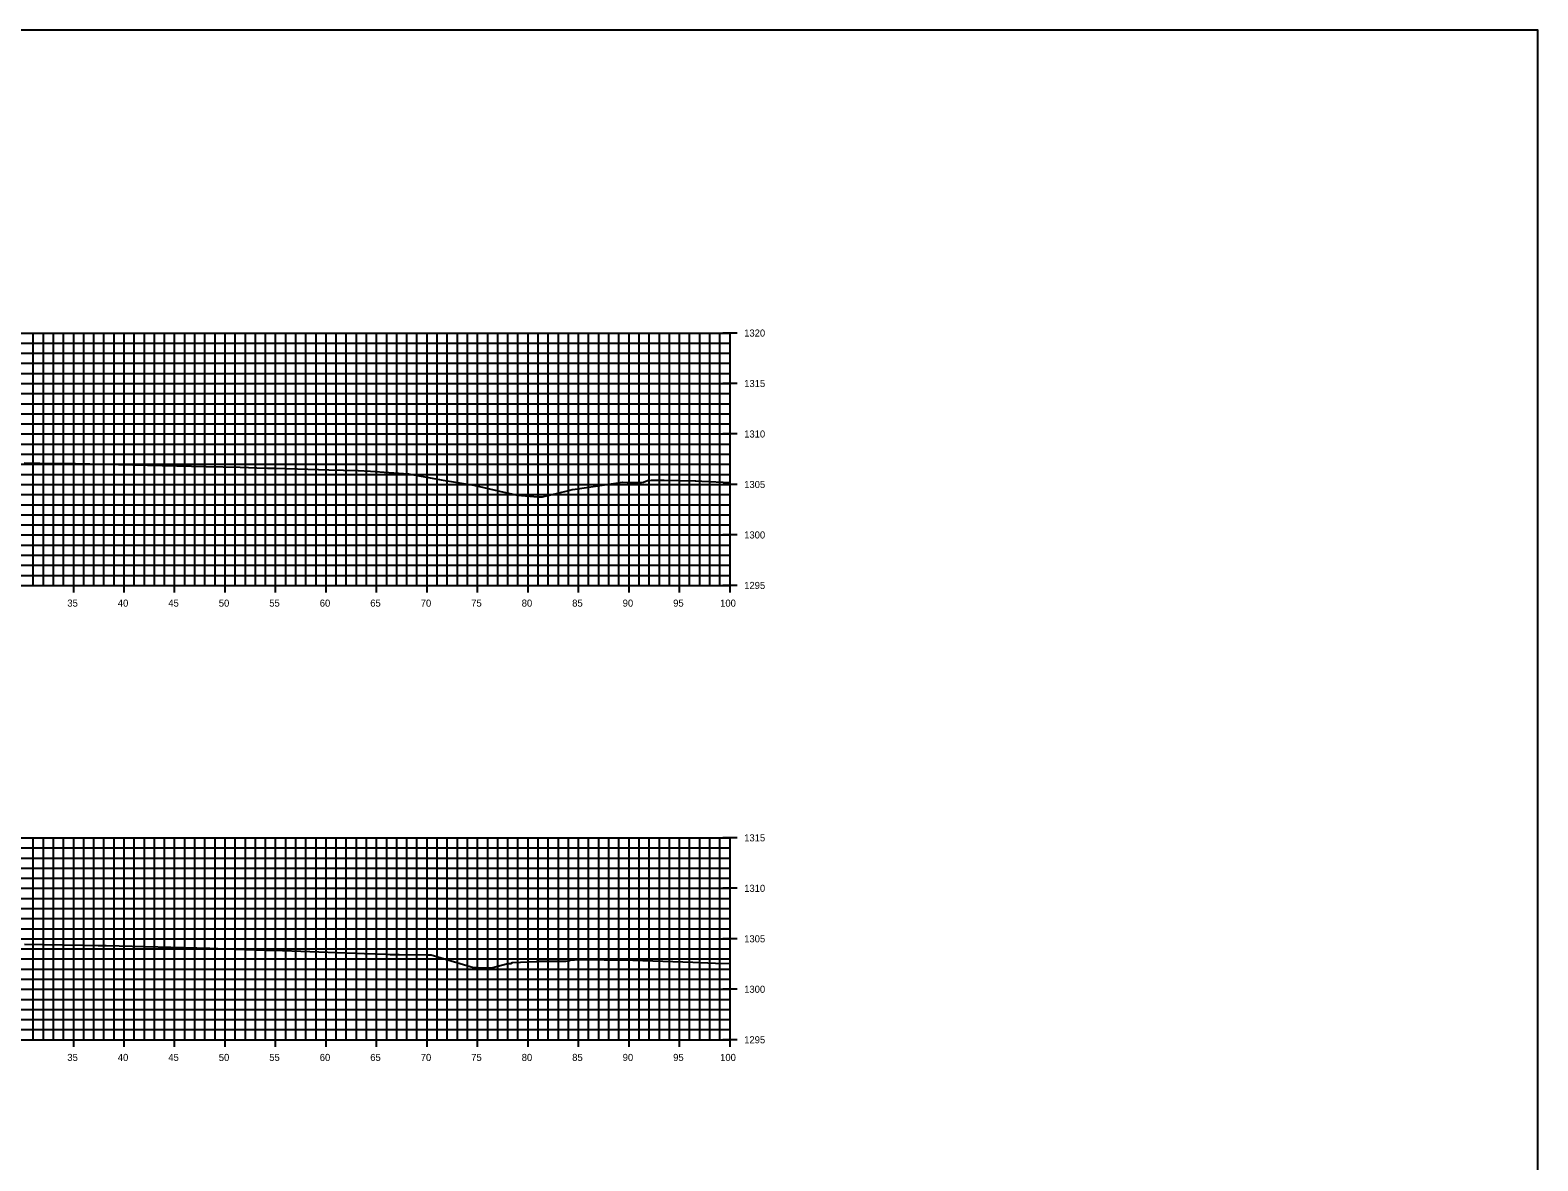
# Model space of a CAD drawing. Extents: x 674939 to 678919, y 750652 to 765176.
# Drawn here: x 678769.2 to 678918.5, y 751030.6 to 751142.6 of the extents above; entities that cross this region are included whole.
import ezdxf

# ---------------------------------------------------------------- set-up
doc = ezdxf.new("R2010")
doc.units = 0
for name, color, linetype in [('R_Axis', 7, 'Continuous'), ('R_Axis Annot', 7, 'Continuous'), ('R_Exist Surface', 7, 'Continuous'), ('R_Grid', 7, 'Continuous'), ('R_No Plot', 7, 'Continuous')]:
    doc.layers.add(name, color=color, linetype=linetype)

msp = doc.modelspace()

# ---------------------------------------------------------------- linework, layer by layer
at = {"layer": 'R_Axis'}
for p, q in [((678839.23, 751112.55), (678837.83, 751112.55)), ((678838.53, 751087.55), (678838.53, 751112.55)), ((678839.23, 751107.55), (678837.83, 751107.55)), ((678839.23, 751102.55), (678837.83, 751102.55)), ((678839.23, 751097.55), (678837.83, 751097.55)), ((678839.23, 751092.55), (678837.83, 751092.55)), ((678773.53, 751086.85), (678773.53, 751088.25)), ((678778.53, 751086.85), (678778.53, 751088.25)), ((678783.53, 751086.85), (678783.53, 751088.25)), ((678788.53, 751086.85), (678788.53, 751088.25)), ((678793.53, 751086.85), (678793.53, 751088.25)), ((678798.53, 751086.85), (678798.53, 751088.25)), ((678803.53, 751086.85), (678803.53, 751088.25)), ((678808.53, 751086.85), (678808.53, 751088.25)), ((678813.53, 751086.85), (678813.53, 751088.25)), ((678818.53, 751086.85), (678818.53, 751088.25)), ((678823.53, 751086.85), (678823.53, 751088.25)), ((678828.53, 751086.85), (678828.53, 751088.25)), ((678833.53, 751086.85), (678833.53, 751088.25)), ((678838.53, 751086.85), (678838.53, 751088.25)), ((678638.53, 751087.55), (678838.53, 751087.55)), ((678839.23, 751087.55), (678837.83, 751087.55)), ((678839.23, 751062.55), (678837.83, 751062.55)), ((678838.53, 751042.55), (678838.53, 751062.55)), ((678839.23, 751057.55), (678837.83, 751057.55)), ((678839.23, 751052.55), (678837.83, 751052.55)), ((678839.23, 751047.55), (678837.83, 751047.55)), ((678773.53, 751041.85), (678773.53, 751043.25)), ((678778.53, 751041.85), (678778.53, 751043.25)), ((678783.53, 751041.85), (678783.53, 751043.25)), ((678788.53, 751041.85), (678788.53, 751043.25)), ((678793.53, 751041.85), (678793.53, 751043.25)), ((678798.53, 751041.85), (678798.53, 751043.25)), ((678803.53, 751041.85), (678803.53, 751043.25)), ((678808.53, 751041.85), (678808.53, 751043.25)), ((678813.53, 751041.85), (678813.53, 751043.25)), ((678818.53, 751041.85), (678818.53, 751043.25)), ((678823.53, 751041.85), (678823.53, 751043.25)), ((678828.53, 751041.85), (678828.53, 751043.25)), ((678833.53, 751041.85), (678833.53, 751043.25)), ((678838.53, 751041.85), (678838.53, 751043.25)), ((678638.53, 751042.55), (678838.53, 751042.55)), ((678839.23, 751042.55), (678837.83, 751042.55))]:
    msp.add_line(p, q, dxfattribs=at)
at = {"layer": 'R_Exist Surface'}
for points in [[(678768.64, 751099.68), (678769.8, 751099.67), (678769.89, 751099.66), (678770.18, 751099.67), (678773.7, 751099.62), (678779.4, 751099.5), (678786.64, 751099.33), (678790.02, 751099.25), (678791.67, 751099.21), (678792.71, 751099.17), (678793.5, 751099.15), (678794.44, 751099.12), (678795.69, 751099.09), (678798.8, 751099.01), (678801.69, 751098.92), (678802.94, 751098.88), (678802.94, 751098.88), (678802.94, 751098.88), (678804.75, 751098.74), (678806.7, 751098.61), (678809.93, 751098), (678813.17, 751097.47), (678816.14, 751096.78), (678817.49, 751096.48), (678819.5, 751096.34), (678819.95, 751096.31), (678822.42, 751096.92), (678822.91, 751097.04), (678823.18, 751097.07), (678827.88, 751097.77), (678828.36, 751097.74), (678829.75, 751097.76), (678829.76, 751097.76), (678829.96, 751097.79), (678830.37, 751097.94), (678830.54, 751097.96), (678830.56, 751097.96), (678830.56, 751097.96), (678830.77, 751097.99), (678830.78, 751097.99), (678831.18, 751097.97), (678831.19, 751097.97), (678831.99, 751097.97), (678832.01, 751097.97), (678832.02, 751097.97), (678835.07, 751097.9), (678835.16, 751097.9), (678835.75, 751097.87), (678838.53, 751097.76)], [(678768.66, 751052.02), (678774.53, 751051.93), (678775.94, 751051.9), (678776.61, 751051.89), (678776.76, 751051.88), (678787.01, 751051.61), (678788.62, 751051.57), (678792.64, 751051.43), (678793.24, 751051.41), (678793.32, 751051.41), (678800.5, 751051.16), (678802.34, 751051.1), (678804.45, 751051.02), (678804.87, 751051.01), (678805.19, 751050.98), (678805.52, 751050.99), (678805.67, 751050.99), (678805.74, 751050.99), (678805.76, 751050.99), (678808.59, 751050.96), (678808.92, 751050.95), (678809.26, 751050.86), (678813.11, 751049.72), (678813.53, 751049.71), (678814.9, 751049.67), (678816.54, 751050.09), (678816.82, 751050.09), (678816.99, 751050.2), (678819.35, 751050.31), (678819.44, 751050.33), (678819.51, 751050.33), (678820.48, 751050.35), (678820.5, 751050.35), (678821.07, 751050.34), (678821.11, 751050.34), (678821.13, 751050.35), (678822.26, 751050.34), (678822.63, 751050.4), (678822.81, 751050.46), (678823.04, 751050.47), (678823.05, 751050.48), (678823.12, 751050.48), (678823.43, 751050.5), (678826.05, 751050.47), (678826.8, 751050.46), (678827.16, 751050.47), (678828.89, 751050.44), (678834.84, 751050.23), (678837.09, 751050.15), (678838.53, 751050.09)]]:
    msp.add_lwpolyline(points, dxfattribs=at)
at = {"layer": 'R_Grid'}
for p, q in [((678638.53, 751112.55), (678838.53, 751112.55)), ((678769.53, 751087.55), (678769.53, 751112.55)), ((678770.53, 751087.55), (678770.53, 751112.55)), ((678771.53, 751087.55), (678771.53, 751112.55)), ((678772.53, 751087.55), (678772.53, 751112.55)), ((678773.53, 751087.55), (678773.53, 751112.55)), ((678774.53, 751087.55), (678774.53, 751112.55)), ((678775.53, 751087.55), (678775.53, 751112.55)), ((678776.53, 751087.55), (678776.53, 751112.55)), ((678777.53, 751087.55), (678777.53, 751112.55)), ((678778.53, 751087.55), (678778.53, 751112.55)), ((678779.53, 751087.55), (678779.53, 751112.55)), ((678780.53, 751087.55), (678780.53, 751112.55)), ((678781.53, 751087.55), (678781.53, 751112.55)), ((678782.53, 751087.55), (678782.53, 751112.55)), ((678783.53, 751087.55), (678783.53, 751112.55)), ((678784.53, 751087.55), (678784.53, 751112.55)), ((678785.53, 751087.55), (678785.53, 751112.55)), ((678786.53, 751087.55), (678786.53, 751112.55)), ((678787.53, 751087.55), (678787.53, 751112.55)), ((678788.53, 751087.55), (678788.53, 751112.55)), ((678789.53, 751087.55), (678789.53, 751112.55)), ((678790.53, 751087.55), (678790.53, 751112.55)), ((678791.53, 751087.55), (678791.53, 751112.55)), ((678792.53, 751087.55), (678792.53, 751112.55)), ((678793.53, 751087.55), (678793.53, 751112.55)), ((678794.53, 751087.55), (678794.53, 751112.55)), ((678795.53, 751087.55), (678795.53, 751112.55)), ((678796.53, 751087.55), (678796.53, 751112.55)), ((678797.53, 751087.55), (678797.53, 751112.55)), ((678798.53, 751087.55), (678798.53, 751112.55)), ((678799.53, 751087.55), (678799.53, 751112.55)), ((678800.53, 751087.55), (678800.53, 751112.55)), ((678801.53, 751087.55), (678801.53, 751112.55)), ((678802.53, 751087.55), (678802.53, 751112.55)), ((678803.53, 751087.55), (678803.53, 751112.55)), ((678804.53, 751087.55), (678804.53, 751112.55)), ((678805.53, 751087.55), (678805.53, 751112.55)), ((678806.53, 751087.55), (678806.53, 751112.55)), ((678807.53, 751087.55), (678807.53, 751112.55)), ((678808.53, 751087.55), (678808.53, 751112.55)), ((678809.53, 751087.55), (678809.53, 751112.55)), ((678810.53, 751087.55), (678810.53, 751112.55)), ((678811.53, 751087.55), (678811.53, 751112.55)), ((678812.53, 751087.55), (678812.53, 751112.55)), ((678813.53, 751087.55), (678813.53, 751112.55)), ((678814.53, 751087.55), (678814.53, 751112.55)), ((678815.53, 751087.55), (678815.53, 751112.55)), ((678816.53, 751087.55), (678816.53, 751112.55)), ((678817.53, 751087.55), (678817.53, 751112.55)), ((678818.53, 751087.55), (678818.53, 751112.55)), ((678819.53, 751087.55), (678819.53, 751112.55)), ((678820.53, 751087.55), (678820.53, 751112.55)), ((678821.53, 751087.55), (678821.53, 751112.55)), ((678822.53, 751087.55), (678822.53, 751112.55)), ((678823.53, 751087.55), (678823.53, 751112.55)), ((678824.53, 751087.55), (678824.53, 751112.55)), ((678825.53, 751087.55), (678825.53, 751112.55)), ((678826.53, 751087.55), (678826.53, 751112.55)), ((678827.53, 751087.55), (678827.53, 751112.55)), ((678828.53, 751087.55), (678828.53, 751112.55)), ((678829.53, 751087.55), (678829.53, 751112.55)), ((678830.53, 751087.55), (678830.53, 751112.55)), ((678831.53, 751087.55), (678831.53, 751112.55)), ((678832.53, 751087.55), (678832.53, 751112.55)), ((678833.53, 751087.55), (678833.53, 751112.55)), ((678834.53, 751087.55), (678834.53, 751112.55)), ((678835.53, 751087.55), (678835.53, 751112.55)), ((678836.53, 751087.55), (678836.53, 751112.55)), ((678837.53, 751087.55), (678837.53, 751112.55)), ((678838.53, 751087.55), (678838.53, 751112.55)), ((678638.53, 751111.55), (678838.53, 751111.55)), ((678638.53, 751110.55), (678838.53, 751110.55)), ((678638.53, 751109.55), (678838.53, 751109.55)), ((678638.53, 751108.55), (678838.53, 751108.55)), ((678638.53, 751107.55), (678838.53, 751107.55)), ((678638.53, 751106.55), (678838.53, 751106.55)), ((678638.53, 751105.55), (678838.53, 751105.55)), ((678638.53, 751104.55), (678838.53, 751104.55)), ((678638.53, 751103.55), (678838.53, 751103.55)), ((678638.53, 751102.55), (678838.53, 751102.55)), ((678638.53, 751101.55), (678838.53, 751101.55)), ((678638.53, 751100.55), (678838.53, 751100.55)), ((678638.53, 751099.55), (678838.53, 751099.55)), ((678638.53, 751098.55), (678838.53, 751098.55)), ((678638.53, 751097.55), (678838.53, 751097.55)), ((678638.53, 751096.55), (678838.53, 751096.55)), ((678638.53, 751095.55), (678838.53, 751095.55)), ((678638.53, 751094.55), (678838.53, 751094.55)), ((678638.53, 751093.55), (678838.53, 751093.55)), ((678638.53, 751092.55), (678838.53, 751092.55)), ((678638.53, 751091.55), (678838.53, 751091.55)), ((678638.53, 751090.55), (678838.53, 751090.55)), ((678638.53, 751089.55), (678838.53, 751089.55)), ((678638.53, 751088.55), (678838.53, 751088.55)), ((678638.53, 751087.55), (678838.53, 751087.55)), ((678638.53, 751062.55), (678838.53, 751062.55)), ((678769.53, 751042.55), (678769.53, 751062.55)), ((678770.53, 751042.55), (678770.53, 751062.55)), ((678771.53, 751042.55), (678771.53, 751062.55)), ((678772.53, 751042.55), (678772.53, 751062.55)), ((678773.53, 751042.55), (678773.53, 751062.55)), ((678774.53, 751042.55), (678774.53, 751062.55)), ((678775.53, 751042.55), (678775.53, 751062.55)), ((678776.53, 751042.55), (678776.53, 751062.55)), ((678777.53, 751042.55), (678777.53, 751062.55)), ((678778.53, 751042.55), (678778.53, 751062.55)), ((678779.53, 751042.55), (678779.53, 751062.55)), ((678780.53, 751042.55), (678780.53, 751062.55)), ((678781.53, 751042.55), (678781.53, 751062.55)), ((678782.53, 751042.55), (678782.53, 751062.55)), ((678783.53, 751042.55), (678783.53, 751062.55)), ((678784.53, 751042.55), (678784.53, 751062.55)), ((678785.53, 751042.55), (678785.53, 751062.55)), ((678786.53, 751042.55), (678786.53, 751062.55)), ((678787.53, 751042.55), (678787.53, 751062.55)), ((678788.53, 751042.55), (678788.53, 751062.55)), ((678789.53, 751042.55), (678789.53, 751062.55)), ((678790.53, 751042.55), (678790.53, 751062.55)), ((678791.53, 751042.55), (678791.53, 751062.55)), ((678792.53, 751042.55), (678792.53, 751062.55)), ((678793.53, 751042.55), (678793.53, 751062.55)), ((678794.53, 751042.55), (678794.53, 751062.55)), ((678795.53, 751042.55), (678795.53, 751062.55)), ((678796.53, 751042.55), (678796.53, 751062.55)), ((678797.53, 751042.55), (678797.53, 751062.55)), ((678798.53, 751042.55), (678798.53, 751062.55)), ((678799.53, 751042.55), (678799.53, 751062.55)), ((678800.53, 751042.55), (678800.53, 751062.55)), ((678801.53, 751042.55), (678801.53, 751062.55)), ((678802.53, 751042.55), (678802.53, 751062.55)), ((678803.53, 751042.55), (678803.53, 751062.55)), ((678804.53, 751042.55), (678804.53, 751062.55)), ((678805.53, 751042.55), (678805.53, 751062.55)), ((678806.53, 751042.55), (678806.53, 751062.55)), ((678807.53, 751042.55), (678807.53, 751062.55)), ((678808.53, 751042.55), (678808.53, 751062.55)), ((678809.53, 751042.55), (678809.53, 751062.55)), ((678810.53, 751042.55), (678810.53, 751062.55)), ((678811.53, 751042.55), (678811.53, 751062.55)), ((678812.53, 751042.55), (678812.53, 751062.55)), ((678813.53, 751042.55), (678813.53, 751062.55)), ((678814.53, 751042.55), (678814.53, 751062.55)), ((678815.53, 751042.55), (678815.53, 751062.55)), ((678816.53, 751042.55), (678816.53, 751062.55)), ((678817.53, 751042.55), (678817.53, 751062.55)), ((678818.53, 751042.55), (678818.53, 751062.55)), ((678819.53, 751042.55), (678819.53, 751062.55)), ((678820.53, 751042.55), (678820.53, 751062.55)), ((678821.53, 751042.55), (678821.53, 751062.55)), ((678822.53, 751042.55), (678822.53, 751062.55)), ((678823.53, 751042.55), (678823.53, 751062.55)), ((678824.53, 751042.55), (678824.53, 751062.55)), ((678825.53, 751042.55), (678825.53, 751062.55)), ((678826.53, 751042.55), (678826.53, 751062.55)), ((678827.53, 751042.55), (678827.53, 751062.55)), ((678828.53, 751042.55), (678828.53, 751062.55)), ((678829.53, 751042.55), (678829.53, 751062.55)), ((678830.53, 751042.55), (678830.53, 751062.55)), ((678831.53, 751042.55), (678831.53, 751062.55)), ((678832.53, 751042.55), (678832.53, 751062.55)), ((678833.53, 751042.55), (678833.53, 751062.55)), ((678834.53, 751042.55), (678834.53, 751062.55)), ((678835.53, 751042.55), (678835.53, 751062.55)), ((678836.53, 751042.55), (678836.53, 751062.55)), ((678837.53, 751042.55), (678837.53, 751062.55)), ((678838.53, 751042.55), (678838.53, 751062.55)), ((678638.53, 751061.55), (678838.53, 751061.55)), ((678638.53, 751060.55), (678838.53, 751060.55)), ((678638.53, 751059.55), (678838.53, 751059.55)), ((678638.53, 751058.55), (678838.53, 751058.55)), ((678638.53, 751057.55), (678838.53, 751057.55)), ((678638.53, 751056.55), (678838.53, 751056.55)), ((678638.53, 751055.55), (678838.53, 751055.55)), ((678638.53, 751054.55), (678838.53, 751054.55)), ((678638.53, 751053.55), (678838.53, 751053.55)), ((678638.53, 751052.55), (678838.53, 751052.55)), ((678638.53, 751051.55), (678838.53, 751051.55)), ((678638.53, 751050.55), (678838.53, 751050.55)), ((678638.53, 751049.55), (678838.53, 751049.55)), ((678638.53, 751048.55), (678838.53, 751048.55)), ((678638.53, 751047.55), (678838.53, 751047.55)), ((678638.53, 751046.55), (678838.53, 751046.55)), ((678638.53, 751045.55), (678838.53, 751045.55)), ((678638.53, 751044.55), (678838.53, 751044.55)), ((678638.53, 751043.55), (678838.53, 751043.55)), ((678638.53, 751042.55), (678838.53, 751042.55))]:
    msp.add_line(p, q, dxfattribs=at)
at = {"layer": 'R_No Plot'}
msp.add_lwpolyline([(678578.53, 750922.55), (678918.53, 750922.55), (678918.53, 751142.55), (678578.53, 751142.55)], close=True, dxfattribs=at)

# ---------------------------------------------------------------- texts
at = {"layer": 'R_Axis Annot'}
for s, p in [('1320', (678839.93, 751112.2)), ('1315', (678839.93, 751107.2)), ('1310', (678839.93, 751102.2)), ('1305', (678839.93, 751097.2)), ('1300', (678839.93, 751092.2)), ('1295', (678839.93, 751087.2)), ('35', (678772.9, 751085.45)), ('40', (678777.9, 751085.45)), ('45', (678782.9, 751085.45)), ('50', (678787.9, 751085.45)), ('55', (678792.9, 751085.45)), ('60', (678797.9, 751085.45)), ('65', (678802.9, 751085.45)), ('70', (678807.9, 751085.45)), ('75', (678812.9, 751085.45)), ('80', (678817.9, 751085.45)), ('85', (678822.9, 751085.45)), ('90', (678827.9, 751085.45)), ('95', (678832.9, 751085.45)), ('100', (678837.55, 751085.45)), ('1315', (678839.93, 751062.2)), ('1310', (678839.93, 751057.2)), ('1305', (678839.93, 751052.2)), ('1300', (678839.93, 751047.2)), ('1295', (678839.93, 751042.2)), ('35', (678772.9, 751040.45)), ('40', (678777.9, 751040.45)), ('45', (678782.9, 751040.45)), ('50', (678787.9, 751040.45)), ('55', (678792.9, 751040.45)), ('60', (678797.9, 751040.45)), ('65', (678802.9, 751040.45)), ('70', (678807.9, 751040.45)), ('75', (678812.9, 751040.45)), ('80', (678817.9, 751040.45)), ('85', (678822.9, 751040.45)), ('90', (678827.9, 751040.45)), ('95', (678832.9, 751040.45)), ('100', (678837.55, 751040.45))]:
    msp.add_text(s, height=0.7, dxfattribs=at).set_placement(p)

doc.saveas('drawing.dxf')
